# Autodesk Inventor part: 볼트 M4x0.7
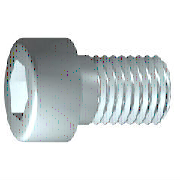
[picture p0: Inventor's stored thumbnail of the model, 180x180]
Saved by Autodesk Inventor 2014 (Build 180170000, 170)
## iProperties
IsCustomPart: 1
Created: 2015-10
Part Number: 볼트 M4x0.7
Material: 스테인리스강
Description: 6각머리 태핑 나사
Document SubType Name: Modeling
Standard: KS B 1003
Designer: mdu
Standards Organization: KS
Language: ko-KR
Size Designation: M 4 x 16
Categories: <MemberInstance><Categories><Category DisplayName="조임쇠" InternalName="e4da775c-781d-43d5-af7c-5136215cf5a6" Mnemonic="FSTN"><Category DisplayName="볼트" InternalN
Density: 8.08 g/cm^3
Mass: 2.70334 g
Surface Area: 3.81118 cm^2
Volume: 0.334572 cm^3
Appearance: 반광택
Author: mdu
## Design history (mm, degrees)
sketch "스케치1"
  geometry: L1 (-1, 0)-(14, 0); L2 (14, 0)-(14, 2); L3 (14, 2)-(1.75, 2); L4 (1.75, 2)-(1.32, 2); L5 (1.32, 2)-(0, 2); L6 (0, 2)-(0, 3.5); L7 (0, 3.5)-(-4, 3.5); L8 (-4, 3.5)-(-4, 1.732); L9 (-4, 1.732)-(-2, 1.732); L10 (-2, 1.732)-(-1, 0); L11 (-7.6, 0)-(17.6, 0) reference; L12 (0, -0.7)-(0, 4.2) reference; L13 (1.75, 2)-(0, 2)
  constraints: 22 end point, 6 parallel, 2 collinear, 2 perpendicular, 1 horizontal, 1 point on line
  dimensions: "d1" = 12.25 distance from line of L3.end L2 (= GEL); "d2" = 0.42952 distance of L4.end L3.end (computed from GAL); "d3" = 4 distance between parallel lines of L8 L6 (= KOH); "d4" = 2 distance of L8.end L9.end (= INTI); "d5" = 60 deg angle of L10 L1; "d6" = 4 diameter of L3 L1 (= GD); "d7" = 4 diameter of L5 L1 (= BDM); "d8" = 3.4641 diameter of L9 L1 (= 1.1547 x SW); "d9" = 7 diameter of L7 L1 (= KOD); "d26" = 14 distance between parallel lines of L12 L2 (= NLG)
revolve "본체" sketch "스케치1" stored, may be unused: angle "d10" = 90 deg
sketch "스케치2"
  geometry: L1 (0, -4.9)-(0, 4.9) reference; L2 (-4.9, 0)-(4.9, 0) reference; L3 (1.732, 0)-(0.866, -1.5); L4 (0.866, -1.5)-(-0.866, -1.5); L5 (-0.866, -1.5)-(-1.732, 0); L6 (-1.732, 0)-(-0.866, 1.5); L7 (-0.866, 1.5)-(0.866, 1.5); L8 (0.866, 1.5)-(1.732, 0); 2 further points
  constraints: 12 end point, 1 coincident, 1 horizontal alignment, 1 point on line, 12 other
extrude "슬롯" join sketch "스케치2" stored distance "d11" = 10; taper "d12" = 0 deg
workplane "Work Plane1"
fillet "Fillet2" dims "d30" = 0.1 (= R)
body "Solid1"
fillet "모깎기1" dims "d17" = 0.4 (= RR)
feature "스레드" dims "d13" = 12.25 (= GEL), "d14" = 0
chamfer "모따기1" distance "d15" = 0.42941 (= -0.5 x SPD + 0.5 x GD); stored, may be unused: second distance "d16" = 0.42941 (= GUL), angle "d27" = 45 deg
other parameters: "GD" = 4 (= NND) [user parameter; used in 2 equation terms], "NLG" = 14 [user parameter; used in 1 equation term], "GEL" = 12.25 [user parameter; used in 2 equation terms], "KOD" = 7 [user parameter; used in 1 equation term], "KOH" = 4 [user parameter; used in 1 equation term], "INTI" = 2 [user parameter; used in 1 equation term], "GAL" = 0.42941 (= 0.61345 x PTC) [user parameter; used in 1 equation term], "GUL" = 0.42941 (= 0.61345 x PTC) [user parameter; used in 1 equation term], "BDM" = 4 (= NND) [user parameter; used in 1 equation term], "SW" = 3 [user parameter; used in 2 equation terms], "RR" = 0.4 [user parameter; used in 1 equation term], "SPD" = 3.14117 (= NND - 1.2269 x PTC) [user parameter; used in 1 equation term], "d19" = 0, "d28" = 0, "d29" = 0, "R" = 0.1 [user parameter; used in 1 equation term], "PHH" = 0.2 [user parameter], "GD1" = 3.14117 (= THREADDIA - 1.2269 x PTC) [user parameter], "THREADDIA" = 4 [user parameter; used in 1 equation term], "FAWI" = 45 deg [user parameter], "TPU" = 14.28571 (computed from PTC) [user parameter], "PTC" = 0.7 [user parameter; used in 5 equation terms], "NND" = 4 [user parameter; used in 3 equation terms], "TOA" = 30 deg [user parameter], "E0" = 3.465 (= 1.155 x SW) [user parameter]
